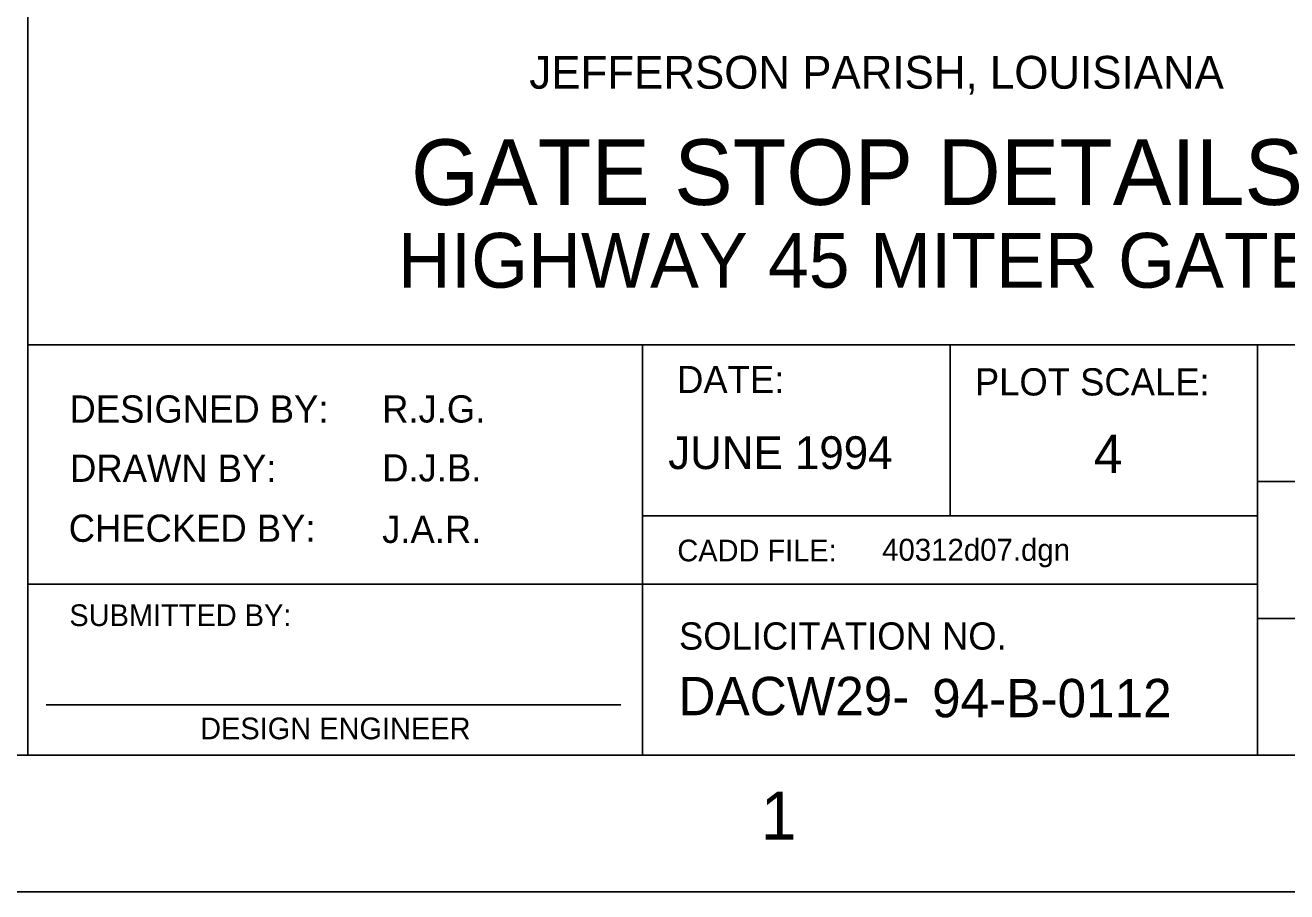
# Model space of a CAD drawing. Extents: x 0.1 to 13.5, y 0.1 to 9.5.
# Drawn here: x 11.122 to 12.661, y 0.125 to 1.181 of the extents above; entities that cross this region are included whole.
import ezdxf

# ---------------------------------------------------------------- set-up
doc = ezdxf.new("R2010")
doc.units = 0
doc.layers.add('Level 1', color=7, linetype='Continuous')
doc.layers.add('Level 2', color=7, linetype='Continuous')

msp = doc.modelspace()

# ---------------------------------------------------------------- linework, layer by layer
at = {"layer": 'Level 1'}
for p, q in [((11.125, 0.2917), (11.125, 1.875)), ((13.2917, 0.7917), (11.125, 0.7917)), ((11.875, 0.2917), (11.875, 0.7917)), ((12.25, 0.5833), (12.25, 0.7917)), ((12.625, 0.2917), (12.625, 0.7917)), ((13.2917, 0.625), (12.625, 0.625)), ((12.625, 0.5833), (11.875, 0.5833)), ((11.125, 0.5), (11.875, 0.5)), ((12.625, 0.5), (11.875, 0.5)), ((13.2917, 0.4583), (12.625, 0.4583)), ((11.1474, 0.3528), (11.8484, 0.3528))]:
    msp.add_line(p, q, dxfattribs=at)
for points in [[(0.125, 9.4583), (13.4583, 9.4583), (13.4583, 0.125), (0.125, 0.125)], [(0.625, 9.2917), (13.2917, 9.2917), (13.2917, 0.2917), (0.625, 0.2917)]]:
    msp.add_lwpolyline(points, close=True, dxfattribs=at)

# ---------------------------------------------------------------- texts
for s, height, p in [('DATE:', 0.03321, (11.917, 0.7329)), ('PLOT SCALE:', 0.033208, (12.2802, 0.73)), ('DESIGNED BY:', 0.033208, (11.176, 0.6969)), ('DRAWN BY:', 0.03321, (11.1767, 0.6247)), ('CHECKED BY:', 0.033208, (11.175, 0.5516)), ('CADD FILE:', 0.02642, (11.9173, 0.5278)), ('SUBMITTED BY:', 0.026417, (11.1758, 0.4489)), ('SOLICITATION NO.', 0.033208, (11.9193, 0.4202)), ('DACW29-', 0.04679, (11.9187, 0.3402)), ('DESIGN ENGINEER', 0.026417, (11.3353, 0.3109)), ('1', 0.0584, (12.0192, 0.1887))]:
    msp.add_text(s, height=height, dxfattribs=at).set_placement(p)
at = {"layer": 'Level 2'}
for s, height, p in [('JEFFERSON PARISH, LOUISIANA', 0.04, (11.7368, 1.104)), ('GATE STOP DETAILS', 0.08, (11.5925, 0.9623)), ('HIGHWAY 45 MITER GATE', 0.066792, (11.5765, 0.8614)), ('R.J.G.', 0.03321, (11.5573, 0.697)), ('JUNE 1994', 0.04, (11.9062, 0.6403)), ('4', 0.0468, (12.4254, 0.6354)), ('D.J.B.', 0.03321, (11.5573, 0.6252)), ('J.A.R.', 0.03321, (11.5573, 0.5502)), ('40312d07.dgn', 0.026792, (12.1671, 0.5285)), ('94-B-0112', 0.04679, (12.228, 0.3377))]:
    msp.add_text(s, height=height, dxfattribs=at).set_placement(p)

doc.saveas('drawing.dxf')
